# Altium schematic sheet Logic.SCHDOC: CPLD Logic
size B; Engineer: Fred Keske; Organization: UH - Institute for Astonomy; Address1: 640 N. Aohoku Place; Address2: Hilo, HI 96720; Address3: USA; DocumentNumber: TCS3 - CPLD; Revision: B; SheetNumber: 1; SheetTotal: 1; PageSetup: Record=PageOptions|CenterHorizontal=True|CenterVertical=True|PrintScale=1.09|XCorrection=1.00|YCorrection=1.00|PrintKind=0|BorderSize=5000000|LeftOffset=0|BottomOffset=0|Orientation=2|PaperLength=1000|PaperWidth=1000|Scale=100|PaperSource=7|PrintQuality=600|MediaType=1|DitherType=10|PaperKind=11x17|PrintScaleMode=1
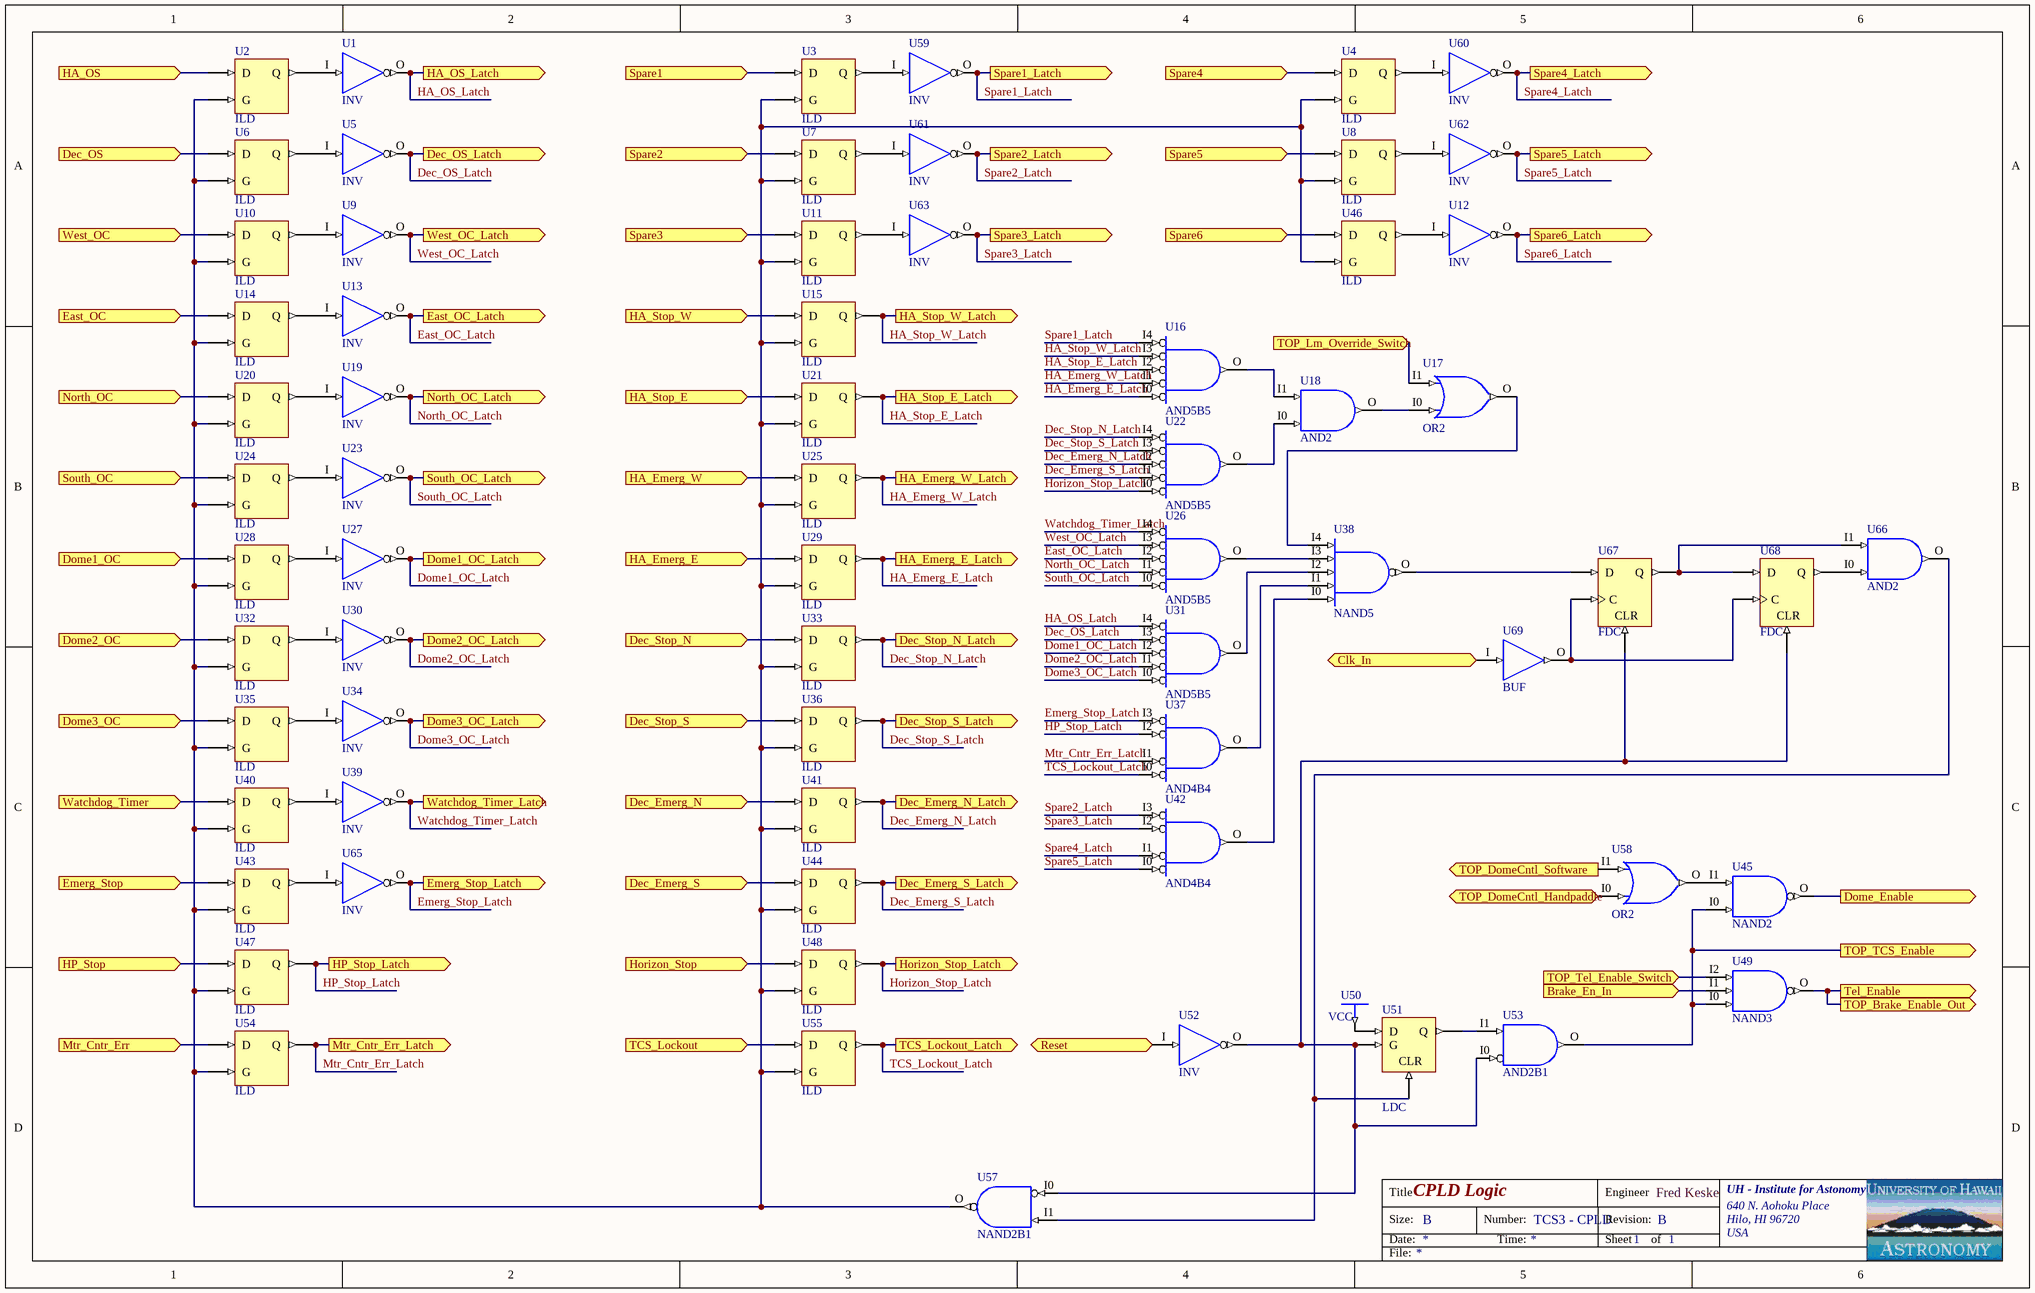
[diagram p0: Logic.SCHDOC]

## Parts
U1  INV
U2  ILD
U3  ILD
U4  ILD
U5  INV
U6  ILD
U7  ILD
U8  ILD
U9  INV
U10  ILD
U11  ILD
U12  INV
U13  INV
U14  ILD
U15  ILD
U16  AND5B5
U17  OR2
U18  AND2
U19  INV
U20  ILD
U21  ILD
U22  AND5B5
U23  INV
U24  ILD
U25  ILD
U26  AND5B5
U27  INV
U28  ILD
U29  ILD
U30  INV
U31  AND5B5
U32  ILD
U33  ILD
U34  INV
U35  ILD
U36  ILD
U37  AND4B4
U38  NAND5
U39  INV
U40  ILD
U41  ILD
U42  AND4B4
U43  ILD
U44  ILD
U45  NAND2
U46  ILD
U47  ILD
U48  ILD
U49  NAND3
U50  VCC
U51  LDC
U52  INV
U53  AND2B1
U54  ILD
U55  ILD
U57  NAND2B1
U58  OR2
U59  INV
U60  INV
U61  INV
U62  INV
U63  INV
U65  INV
U66  AND2
U67  FDC
U68  FDC
U69  BUF

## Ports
Brake_En_In (in), Clk_In (in), Dec_Emerg_N (in), Dec_Emerg_N_Latch (out), Dec_Emerg_S (in), Dec_Emerg_S_Latch (out), Dec_OS (in), Dec_OS_Latch (out), Dec_Stop_N (in), Dec_Stop_N_Latch (out), Dec_Stop_S (in), Dec_Stop_S_Latch (out), Dome1_OC (in), Dome1_OC_Latch (out), Dome2_OC (in), Dome2_OC_Latch (out), Dome3_OC (in), Dome3_OC_Latch (out), Dome_Enable (out), East_OC (in), East_OC_Latch (out), Emerg_Stop (in), Emerg_Stop_Latch (out), HA_Emerg_E (in), HA_Emerg_E_Latch (out), HA_Emerg_W (in), HA_Emerg_W_Latch (out), HA_OS (in), HA_OS_Latch (out), HA_Stop_E (in), HA_Stop_E_Latch (out), HA_Stop_W (in), HA_Stop_W_Latch (out), Horizon_Stop (in), Horizon_Stop_Latch (out), HP_Stop (in), HP_Stop_Latch (out), Mtr_Cntr_Err (in), Mtr_Cntr_Err_Latch (out), North_OC (in), North_OC_Latch (out), Reset (in), South_OC (in), South_OC_Latch (out), Spare1 (in), Spare1_Latch (out), Spare2 (in), Spare2_Latch (out), Spare3 (in), Spare3_Latch (out), Spare4 (in), Spare4_Latch (out), Spare5 (in), Spare5_Latch (out), Spare6 (in), Spare6_Latch (out), TCS_Lockout (in), TCS_Lockout_Latch (out), Tel_Enable (out), TOP_Brake_Enable_Out (out), TOP_DomeCntl_Handpaddle (in), TOP_DomeCntl_Software (in), TOP_Lm_Override_Switch (in), TOP_TCS_Enable (out), TOP_Tel_Enable_Switch (in), Watchdog_Timer (in), Watchdog_Timer_Latch (out), West_OC (in), West_OC_Latch (out)

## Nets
Brake_En_In: U49.I1 ; port Brake_En_In
Clk_In: U69.I ; port Clk_In
Dec_Emerg_N: U41.D ; port Dec_Emerg_N
Dec_Emerg_N_Latch: U22.I2 U41.Q ; port Dec_Emerg_N_Latch
Dec_Emerg_S: U44.D ; port Dec_Emerg_S
Dec_Emerg_S_Latch: U22.I1 U44.Q ; port Dec_Emerg_S_Latch
Dec_OS: U6.D ; port Dec_OS
Dec_OS_Latch: U5.O U31.I3 ; port Dec_OS_Latch
Dec_Stop_N: U33.D ; port Dec_Stop_N
Dec_Stop_N_Latch: U22.I4 U33.Q ; port Dec_Stop_N_Latch
Dec_Stop_S: U36.D ; port Dec_Stop_S
Dec_Stop_S_Latch: U22.I3 U36.Q ; port Dec_Stop_S_Latch
Dome1_OC: U28.D ; port Dome1_OC
Dome1_OC_Latch: U27.O U31.I2 ; port Dome1_OC_Latch
Dome2_OC: U32.D ; port Dome2_OC
Dome2_OC_Latch: U30.O U31.I1 ; port Dome2_OC_Latch
Dome3_OC: U35.D ; port Dome3_OC
Dome3_OC_Latch: U31.I0 U34.O ; port Dome3_OC_Latch
Dome_Enable: U45.O ; port Dome_Enable
East_OC: U14.D ; port East_OC
East_OC_Latch: U13.O U26.I2 ; port East_OC_Latch
Emerg_Stop: U43.D ; port Emerg_Stop
Emerg_Stop_Latch: U37.I3 U65.O ; port Emerg_Stop_Latch
HA_Emerg_E: U29.D ; port HA_Emerg_E
HA_Emerg_E_Latch: U16.I0 U29.Q ; port HA_Emerg_E_Latch
HA_Emerg_W: U25.D ; port HA_Emerg_W
HA_Emerg_W_Latch: U16.I1 U25.Q ; port HA_Emerg_W_Latch
HA_OS: U2.D ; port HA_OS
HA_OS_Latch: U1.O U31.I4 ; port HA_OS_Latch
HA_Stop_E: U21.D ; port HA_Stop_E
HA_Stop_E_Latch: U16.I2 U21.Q ; port HA_Stop_E_Latch
HA_Stop_W: U15.D ; port HA_Stop_W
HA_Stop_W_Latch: U15.Q U16.I3 ; port HA_Stop_W_Latch
Horizon_Stop: U48.D ; port Horizon_Stop
Horizon_Stop_Latch: U22.I0 U48.Q ; port Horizon_Stop_Latch
HP_Stop: U47.D ; port HP_Stop
HP_Stop_Latch: U37.I2 U47.Q ; port HP_Stop_Latch
Mtr_Cntr_Err: U54.D ; port Mtr_Cntr_Err
Mtr_Cntr_Err_Latch: U37.I1 U54.Q ; port Mtr_Cntr_Err_Latch
North_OC: U20.D ; port North_OC
North_OC_Latch: U19.O U26.I1 ; port North_OC_Latch
Reset: U52.I ; port Reset
South_OC: U24.D ; port South_OC
South_OC_Latch: U23.O U26.I0 ; port South_OC_Latch
Spare1: U3.D ; port Spare1
Spare1_Latch: U16.I4 U59.O ; port Spare1_Latch
Spare2: U7.D ; port Spare2
Spare2_Latch: U42.I3 U61.O ; port Spare2_Latch
Spare3: U11.D ; port Spare3
Spare3_Latch: U42.I2 U63.O ; port Spare3_Latch
Spare4: U4.D ; port Spare4
Spare4_Latch: U42.I1 U60.O ; port Spare4_Latch
Spare5: U8.D ; port Spare5
Spare5_Latch: U42.I0 U62.O ; port Spare5_Latch
Spare6: U46.D ; port Spare6
Spare6_Latch: U12.O ; port Spare6_Latch
TCS_Lockout: U55.D ; port TCS_Lockout
TCS_Lockout_Latch: U37.I0 U55.Q ; port TCS_Lockout_Latch
Tel_Enable: U49.O ; port TOP_Brake_Enable_Out, port Tel_Enable
TOP_DomeCntl_Handpaddle: U58.I0 ; port TOP_DomeCntl_Handpaddle
TOP_DomeCntl_Software: U58.I1 ; port TOP_DomeCntl_Software
TOP_Lm_Override_Switch: U17.I1 ; port TOP_Lm_Override_Switch
TOP_TCS_Enable: U45.I0 U49.I0 U53.O ; port TOP_TCS_Enable
TOP_Tel_Enable_Switch: U49.I2 ; port TOP_Tel_Enable_Switch
Watchdog_Timer: U40.D ; port Watchdog_Timer
Watchdog_Timer_Latch: U26.I4 U39.O ; port Watchdog_Timer_Latch
West_OC: U10.D ; port West_OC
West_OC_Latch: U9.O U26.I3 ; port West_OC_Latch
NetU1_I: U1.I U2.Q
NetU2_G: U2.G U3.G U4.G U6.G U7.G U8.G U10.G U11.G U14.G U15.G U20.G U21.G U24.G U25.G U28.G U29.G U32.G U33.G U35.G U36.G U40.G U41.G U43.G U44.G U46.G U47.G U48.G U54.G U55.G U57.O
NetU3_Q: U3.Q U59.I
NetU4_Q: U4.Q U60.I
NetU5_I: U5.I U6.Q
NetU7_Q: U7.Q U61.I
NetU8_Q: U8.Q U62.I
NetU9_I: U9.I U10.Q
NetU11_Q: U11.Q U63.I
NetU12_I: U12.I U46.Q
NetU13_I: U13.I U14.Q
NetU16_O: U16.O U18.I1
NetU17_I0: U17.I0 U18.O
NetU17_O: U17.O U38.I4
NetU18_I0: U18.I0 U22.O
NetU19_I: U19.I U20.Q
NetU23_I: U23.I U24.Q
NetU26_O: U26.O U38.I3
NetU27_I: U27.I U28.Q
NetU30_I: U30.I U32.Q
NetU31_O: U31.O U38.I2
NetU34_I: U34.I U35.Q
NetU37_O: U37.O U38.I1
NetU38_I0: U38.I0 U42.O
NetU38_O: U38.O U67.D
NetU39_I: U39.I U40.Q
NetU43_Q: U43.Q U65.I
NetU45_I1: U45.I1 U58.O
NetU50_P: U50.P U51.D
NetU51_CLR: U51.CLR U57.I1 U66.O
NetU51_G: U51.G U52.O U53.I0 U57.I0 U67.CLR U68.CLR
NetU51_Q: U51.Q U53.I1
NetU66_I0: U66.I0 U68.Q
NetU66_I1: U66.I1 U67.Q U68.D
NetU67_C: U67.C U68.C U69.O

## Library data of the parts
U1 U5 U9 U12 U13 U19 U23 U27 U30 U34 U39 U52 U59-U63 U65 = INV: Inverter; FPGAVendor: Xilinx
U2-U4 U6-U8 U10 U11 U14 U15 U20 U21 U24 U25 U28 U29 U32 U33 U35 U36 U40 U41 U43 U44 U46-U48 U54 U55 = ILD: Transparent Input Data Latch; FPGAVendor: Xilinx
U16 U22 U26 U31 = AND5B5: 5-Input AND Gate with Five Inverted Inputs; FPGAVendor: Xilinx
U17 U58 = OR2: 2-Input OR Gate; FPGAVendor: Xilinx
U18 U66 = AND2: 2-Input AND Gate; FPGAVendor: Xilinx
U37 U42 = AND4B4: 4-Input AND Gate with Four Inverted Inputs; FPGAVendor: Xilinx
U38 = NAND5: 5-Input NAND Gate; FPGAVendor: Xilinx
U45 = NAND2: 2-Input NAND Gate; FPGAVendor: Xilinx
U49 = NAND3: 3-Input NAND Gate; FPGAVendor: Xilinx
U50 = VCC: VCC-Connection Signal Tag; FPGAVendor: Xilinx
U51 = LDC: Transparent Data Latch with Asynchronous Clear; FPGAVendor: Xilinx
U53 = AND2B1: 2-Input AND Gate with One Inverted Input; FPGAVendor: Xilinx
U57 = NAND2B1: 2-Input NAND Gate with One Inverted Input; FPGAVendor: Xilinx
U67 U68 = FDC: D Flip-Flop with Asynchronous Clear; FPGAVendor: Xilinx
U69 = BUF: Global Clock Buffer; FPGAVendor: Xilinx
